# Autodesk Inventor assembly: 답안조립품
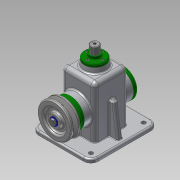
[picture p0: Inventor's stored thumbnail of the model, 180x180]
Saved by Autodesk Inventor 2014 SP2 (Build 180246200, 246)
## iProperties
Created: 2016-08
Part Number: 답안조립품
Document SubType Name: Assembly
Designer: user
Author: user
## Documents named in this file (19)
- C:\Users\user\Desktop\460820V1007\답안조립품.iam
- C:\Users\user\Desktop\460820V1007\본체.ipt
- C:\Users\user\Desktop\460820V1007\뒤커버.ipt
- C:\Users\user\Desktop\460820V1007\앞커버.ipt
- C:\Users\user\Desktop\460820V1007\상부부시.ipt
- C:\Users\user\Desktop\460820V1007\베어링 15 x 35 x 11.ipt
- C:\Users\user\Desktop\460820V1007\오일실 15 25 7.ipt
- C:\Users\user\Desktop\460820V1007\편심축.ipt
- C:\Users\user\Desktop\460820V1007\키 5 x 5 x 14.ipt
- C:\Users\user\Desktop\460820V1007\링크.ipt
- C:\Users\user\Desktop\460820V1007\슬라이드바.ipt
- C:\Users\user\Desktop\460820V1007\V-벨트풀리.ipt
- C:\Users\user\Desktop\460820V1007\고정핀.ipt
- C:\Users\user\Desktop\460820V1007\멈춤링 6 x 5.ipt
- C:\Users\user\Desktop\460820V1007\멈춤링 15 x 1.ipt
- C:\Users\user\Desktop\460820V1007\볼트 M4 x 10.ipt
- C:\Users\user\Desktop\460820V1007\볼트 M3 x 8.ipt
- C:\Users\user\Desktop\460820V1007\볼트 M6 x 12.ipt
- C:\Users\user\Desktop\460820V1007\와셔.ipt
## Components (15 placed, 5 different names)
1. V-벨트풀리:1 — 각도:1
2. 고정핀:1 — 강체:1, 강체:5, 강체:2
3. ISO 4018 M6 x 12:1 — 강체:10
4. ISO 4762 M4 x 10:1 — 강체:6
5. ISO 4762 M4 x 10:2 — 강체:7
6. ISO 4762 M4 x 10:3
7. ISO 4762 M4 x 10:4
8. ISO 4762 M4 x 10:5
9. ISO 4762 M4 x 10:6
10. ISO 4762 M4 x 10:7
11. ISO 4762 M4 x 10:8
12. ISO 4762 M3 x 8:1 — 강체:8
13. ISO 4762 M3 x 8:2
14. ISO 4762 M3 x 8:3
15. ISO 4762 M3 x 8:4
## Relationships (8: WeldJoint 7, Angle 1)
- 강체:1 [WeldJoint]: 고정핀:1
- 강체:5 [WeldJoint]: 고정핀:1
- 강체:2 [WeldJoint]: 고정핀:1
- 각도:1 [Angle]: V-벨트풀리:1
- 강체:6 [WeldJoint]: ISO 4762 M4 x 10:1
- 강체:7 [WeldJoint]: ISO 4762 M4 x 10:2
- 강체:8 [WeldJoint]: ISO 4762 M3 x 8:1
- 강체:10 [WeldJoint]: ISO 4018 M6 x 12:1
